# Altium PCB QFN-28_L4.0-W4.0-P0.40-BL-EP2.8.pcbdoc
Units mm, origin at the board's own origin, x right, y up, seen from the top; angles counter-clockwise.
Board outline 17.4 x 17.44 mm, 2 copper layers (Top Layer, Bottom Layer), stack 0 mm thick; 1 components, 0 nets, 29 pads, 0 vias.
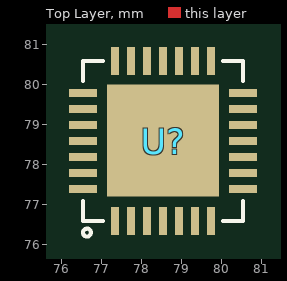
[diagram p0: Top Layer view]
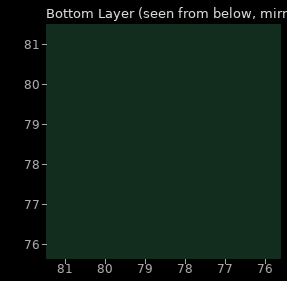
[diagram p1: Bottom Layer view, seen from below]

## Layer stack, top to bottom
Top Layer: signal copper (thickness not stored)
Bottom Layer: signal copper (thickness not stored)

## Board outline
87.25,69.85 69.85,69.85 69.85,87.285 87.25,87.285

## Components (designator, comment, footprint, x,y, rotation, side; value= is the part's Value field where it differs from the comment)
U? "" QFN-28_L4.0-W4.0-P0.40-BL-EP2.8 78.55,78.585 r0 top

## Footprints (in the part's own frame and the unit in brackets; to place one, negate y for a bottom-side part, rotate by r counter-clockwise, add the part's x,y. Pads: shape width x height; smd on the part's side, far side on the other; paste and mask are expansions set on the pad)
QFN-28_L4.0-W4.0-P0.40-BL-EP2.8 [mm]
  rect 0.2x0.7 smd paste-100 mask+0.051: 1(-1.2,-2) 2(-0.8,-2) 3(-0.4,-2) 4(-0.001,-2) 5(0.4,-2) 6(0.8,-2) 7(1.2,-2) 15(1.2,2) 16(0.8,2) 17(0.4,2) 18(0,2) 19(-0.4,2) 20(-0.8,2) 21(-1.2,2)
  rect 0.7x0.2 smd paste-100 mask+0.051: 8(2,-1.2) 9(2,-0.8) 10(2,-0.4) 11(1.999,0) 12(2,0.4) 13(2,0.8) 14(2,1.2) 22(-2,1.2) 23(-2,0.8) 24(-2,0.4) 25(-2,0) 26(-2,-0.4) 27(-2,-0.8) 28(-2,-1.2)
  rect 2.8x2.8 smd paste-100 mask+0.051: 29(0,0.02)
  silkscreen extent -2,-2.38 2,2

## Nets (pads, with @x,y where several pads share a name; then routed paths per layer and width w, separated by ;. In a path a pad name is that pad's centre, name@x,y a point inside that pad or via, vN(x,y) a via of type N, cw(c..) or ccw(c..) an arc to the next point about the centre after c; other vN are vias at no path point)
pads on no net: U?.1 U?.2 U?.3 U?.4 U?.5 U?.6 U?.7 U?.8 U?.9 U?.10 U?.11 U?.12 U?.13 U?.14 U?.15 U?.16 U?.17 U?.18 U?.19 U?.20 U?.21 U?.22 U?.23 U?.24 U?.25 U?.26 U?.27 U?.28 U?.29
